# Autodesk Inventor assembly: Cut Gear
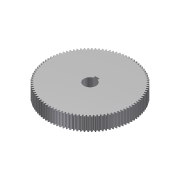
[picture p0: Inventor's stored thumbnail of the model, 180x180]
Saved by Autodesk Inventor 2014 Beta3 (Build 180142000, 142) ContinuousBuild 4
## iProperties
Created: 2011-01
Part Number: Cut Gear
Document SubType Name: Assembly
Designer: Beta-8540w
Categories: <?xml version="1.0" encoding="UTF-16"?> <MemberInstance><Categories><FamilyTemplate/><ParamToTemplateMap><ParamToTemplate><ParamToTemplate CategoryParameter="//
ClientObjectVersion: 1
Author: Beta-8540w
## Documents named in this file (2)
- C:\Inventor 2014 Essentials\Assemblies\Chapter 09\Design Accelerators\Spur Gear c09-01.iam
- C:\Inventor 2014 Essentials\Assemblies\Chapter 09\Design Accelerators\Spur Gear c09-01.ipt
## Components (1 placed, 1 different names)
1. Spur Gear:1
